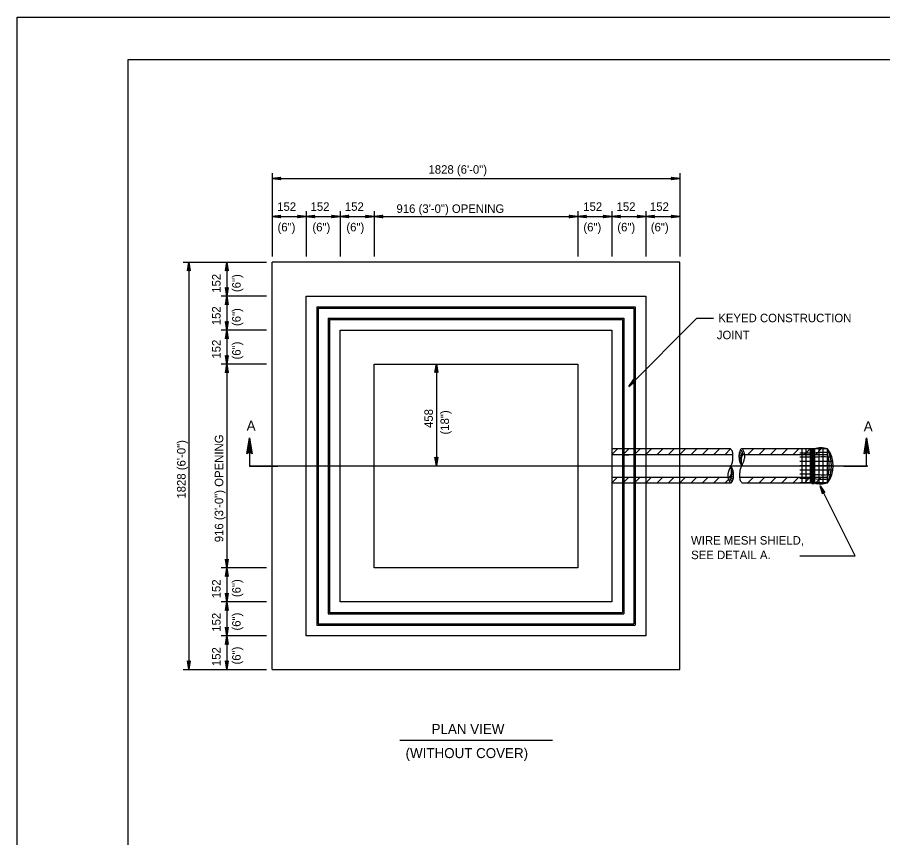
# Model space of a CAD drawing. Extents: x 638443 to 639347, y 298405 to 298999.
# Drawn here: x 638443.3 to 638749, y 298709.2 to 298999 of the extents above; entities that cross this region are included whole.
import ezdxf

# ---------------------------------------------------------------- set-up
doc = ezdxf.new("R2010")
doc.units = 0
for name, color, linetype in [('1', 7, 'Continuous'), ('2', 7, 'Continuous'), ('3', 7, 'Continuous'), ('PLT-BNDY', 7, 'Continuous')]:
    doc.layers.add(name, color=color, linetype=linetype)

msp = doc.modelspace()

# ---------------------------------------------------------------- linework, layer by layer
at = {"layer": '1'}
msp.add_lwpolyline([(639268.31, 298419.95), (639268.31, 298983.95), (638482.31, 298983.95), (638482.31, 298419.95), (639268.31, 298419.95), (639268.31, 298446.31), (639068.31, 298446.31), (639068.31, 298510.99), (639268.31, 298510.99), (639268.31, 298539.95), (639068.31, 298539.95), (639068.31, 298419.95), (639147.11, 298419.95), (639147.11, 298446.31), (639147.11, 298419.95), (639224.11, 298419.95), (639224.11, 298446.31), (639224.11, 298434), (639268.31, 298434)], dxfattribs=at)
at = {"layer": '2'}
for p, q in [((638533.34, 298943.94), (638533.34, 298914.5)), ((638533.34, 298942.07), (638677.34, 298942.07)), ((638677.34, 298943.94), (638677.34, 298914.5)), ((638545.34, 298930.5), (638545.34, 298914.5)), ((638557.34, 298930.5), (638557.34, 298914.5)), ((638569.34, 298930.5), (638569.34, 298914.5)), ((638641.34, 298930.5), (638641.34, 298914.5)), ((638653.34, 298930.5), (638653.34, 298914.5)), ((638665.34, 298930.5), (638665.34, 298914.5)), ((638533.34, 298928.63), (638545.34, 298928.63)), ((638545.34, 298928.63), (638557.34, 298928.63)), ((638557.34, 298928.63), (638569.34, 298928.63)), ((638569.34, 298928.63), (638641.34, 298928.63)), ((638641.34, 298928.63), (638653.34, 298928.63)), ((638653.34, 298928.63), (638665.34, 298928.63)), ((638665.34, 298928.63), (638677.34, 298928.63)), ((638501.88, 298912.5), (638531.34, 298912.5)), ((638503.88, 298912.5), (638503.88, 298768.63)), ((638517.34, 298912.5), (638517.34, 298900.5)), ((638677.34, 298912.5), (638533.34, 298912.5)), ((638533.34, 298768.63), (638533.34, 298912.5)), ((638677.34, 298768.63), (638677.34, 298912.5)), ((638515.34, 298900.63), (638531.34, 298900.63)), ((638517.34, 298900.5), (638517.34, 298888.5)), ((638545.34, 298900.5), (638665.34, 298900.5)), ((638545.34, 298780.5), (638545.34, 298900.5)), ((638665.34, 298900.5), (638665.34, 298780.5)), ((638549.09, 298896.75), (638549.09, 298784.25)), ((638549.09, 298896.75), (638661.59, 298896.75)), ((638549.59, 298896.25), (638549.59, 298784.75)), ((638549.59, 298896.25), (638661.09, 298896.25)), ((638661.09, 298896.25), (638661.09, 298784.75)), ((638661.59, 298896.75), (638661.59, 298784.25)), ((638553.09, 298892.75), (638553.09, 298788.25)), ((638553.09, 298892.75), (638657.59, 298892.75)), ((638657.59, 298892.75), (638657.59, 298788.25)), ((638553.59, 298892.25), (638553.59, 298788.75)), ((638553.59, 298892.25), (638657.09, 298892.25)), ((638657.09, 298892.25), (638657.09, 298788.75)), ((638515.34, 298888.63), (638531.34, 298888.63)), ((638517.34, 298888.5), (638517.34, 298876.5)), ((638557.34, 298888.5), (638653.34, 298888.5)), ((638557.34, 298792.5), (638557.34, 298888.5)), ((638653.34, 298888.5), (638653.34, 298792.5)), ((638515.34, 298876.63), (638531.34, 298876.63)), ((638517.34, 298876.5), (638517.34, 298804.5)), ((638569.34, 298876.5), (638641.34, 298876.5)), ((638569.34, 298804.5), (638569.34, 298876.5)), ((638591.34, 298876.57), (638591.34, 298840.57)), ((638641.34, 298876.5), (638641.34, 298804.5)), ((638525.34, 298850.5), (638525.34, 298840.5)), ((638743.34, 298840.5), (638743.34, 298850.5)), ((638653.34, 298844.57), (638655.34, 298846.57)), ((638663.26, 298846.57), (638653.34, 298846.57)), ((638657.34, 298844.57), (638659.34, 298846.57)), ((638661.34, 298844.57), (638663.34, 298846.57)), ((638695.29, 298846.57), (638663.26, 298846.57)), ((638665.34, 298844.57), (638667.34, 298846.57)), ((638669.34, 298844.57), (638671.34, 298846.57)), ((638673.34, 298844.57), (638675.34, 298846.57)), ((638677.34, 298844.57), (638679.34, 298846.57)), ((638681.34, 298844.57), (638683.34, 298846.57)), ((638685.34, 298844.57), (638687.34, 298846.57)), ((638689.34, 298844.57), (638691.34, 298846.57)), ((638729.54, 298846.57), (638699.3, 298846.57)), ((638699.3, 298846.52), (638699.34, 298846.57)), ((638701.34, 298844.57), (638703.34, 298846.57)), ((638705.34, 298844.57), (638707.34, 298846.57)), ((638709.34, 298844.57), (638711.34, 298846.57)), ((638713.34, 298844.57), (638715.34, 298846.57)), ((638717.34, 298844.57), (638719.34, 298846.57)), ((638729.54, 298846.57), (638719.77, 298846.57)), ((638720.54, 298834.57), (638720.54, 298846.57)), ((638721.34, 298844.57), (638723.34, 298846.57)), ((638722.04, 298834.57), (638722.04, 298846.57)), ((638723.54, 298834.57), (638723.54, 298846.57)), ((638723.94, 298834.35), (638723.94, 298846.73)), ((638723.94, 298846.73), (638724.8, 298846.73)), ((638723.99, 298834.35), (638723.99, 298846.73)), ((638724.05, 298834.35), (638724.05, 298846.73)), ((638724.12, 298834.35), (638724.12, 298846.73)), ((638724.18, 298834.35), (638724.18, 298846.73)), ((638724.24, 298834.35), (638724.24, 298846.73)), ((638724.3, 298834.35), (638724.3, 298846.73)), ((638724.37, 298834.35), (638724.37, 298846.73)), ((638724.43, 298834.35), (638724.43, 298846.73)), ((638724.49, 298834.35), (638724.49, 298846.73)), ((638724.55, 298834.35), (638724.55, 298846.73)), ((638724.61, 298834.35), (638724.61, 298846.73)), ((638724.68, 298834.35), (638724.68, 298846.73)), ((638724.74, 298834.35), (638724.74, 298846.73)), ((638724.8, 298834.35), (638724.8, 298846.73)), ((638725.04, 298834.57), (638725.04, 298846.57)), ((638725.34, 298844.57), (638727.34, 298846.57)), ((638726.54, 298834.22), (638726.54, 298846.9)), ((638728.04, 298834.25), (638728.04, 298846.87)), ((638729.54, 298834.57), (638729.54, 298846.57)), ((638729.54, 298834.57), (638729.54, 298846.57)), ((638653.34, 298844.57), (638696, 298844.57)), ((638659.34, 298844.31), (638657.34, 298844.31)), ((638693.34, 298844.57), (638695.29, 298846.52)), ((638700.34, 298844.57), (638729.54, 298844.57)), ((638725.05, 298843.57), (638719.7, 298843.57)), ((638724.77, 298845.07), (638719.79, 298845.07)), ((638525.34, 298840.57), (638743.79, 298840.57)), ((638525.34, 298840.5), (638535.34, 298840.5)), ((638731.54, 298840.57), (638719.73, 298840.57)), ((638731.43, 298842.07), (638719.77, 298842.07)), ((638735.34, 298840.5), (638743.34, 298840.5)), ((638731.43, 298839.07), (638719.75, 298839.07)), ((638725.05, 298837.57), (638719.79, 298837.57)), ((638653.34, 298834.57), (638655.34, 298836.57)), ((638653.34, 298836.57), (638694.36, 298836.57)), ((638653.34, 298834.57), (638663.26, 298834.57)), ((638657.34, 298834.57), (638659.34, 298836.57)), ((638661.34, 298834.57), (638663.34, 298836.57)), ((638663.26, 298834.57), (638695.29, 298834.57)), ((638665.34, 298834.57), (638667.34, 298836.57)), ((638669.34, 298834.57), (638671.34, 298836.57)), ((638673.34, 298834.57), (638675.34, 298836.57)), ((638677.34, 298834.57), (638679.34, 298836.57)), ((638681.34, 298834.57), (638683.34, 298836.57)), ((638685.34, 298834.57), (638687.34, 298836.57)), ((638689.34, 298834.57), (638691.34, 298836.57)), ((638693.34, 298834.57), (638694.52, 298835.74)), ((638698.74, 298836.57), (638729.54, 298836.57)), ((638699.3, 298836.52), (638699.34, 298836.57)), ((638699.3, 298834.57), (638729.54, 298834.57)), ((638701.34, 298834.57), (638703.34, 298836.57)), ((638705.34, 298834.57), (638707.34, 298836.57)), ((638709.34, 298834.57), (638711.34, 298836.57)), ((638713.34, 298834.57), (638715.34, 298836.57)), ((638717.34, 298834.57), (638719.34, 298836.57)), ((638724.95, 298836.07), (638719.75, 298836.07)), ((638729.54, 298834.57), (638719.75, 298834.57)), ((638721.34, 298834.57), (638723.34, 298836.57)), ((638725.34, 298834.57), (638727.34, 298836.57)), ((638719.75, 298808.75), (638739.25, 298808.75)), ((638515.34, 298804.63), (638531.34, 298804.63)), ((638517.34, 298804.5), (638517.34, 298792.5)), ((638641.34, 298804.5), (638569.34, 298804.5)), ((638515.34, 298792.63), (638531.34, 298792.63)), ((638517.34, 298792.5), (638517.34, 298780.5)), ((638653.34, 298792.5), (638557.34, 298792.5)), ((638553.59, 298788.75), (638657.09, 298788.75)), ((638553.09, 298788.25), (638657.59, 298788.25)), ((638549.09, 298784.25), (638661.59, 298784.25)), ((638549.59, 298784.75), (638661.09, 298784.75)), ((638515.34, 298780.63), (638531.34, 298780.63)), ((638517.34, 298780.5), (638517.34, 298768.63)), ((638665.34, 298780.5), (638545.34, 298780.5)), ((638501.88, 298768.63), (638531.34, 298768.63)), ((638677.34, 298768.5), (638533.34, 298768.5)), ((638578.42, 298743.72), (638632.32, 298743.72))]:
    msp.add_line(p, q, dxfattribs=at)
for points in [[(638638.44, 298928.99), (638638.54, 298928.78), (638641.34, 298928.63), (638638.44, 298928.99), (638638.29, 298929.12), (638641.34, 298928.63), (638638.55, 298928.49), (638638.44, 298928.28), (638641.34, 298928.63), (638638.29, 298928.14), (638638.44, 298928.28)], [(638644.25, 298928.27), (638644.14, 298928.48), (638641.34, 298928.63), (638644.25, 298928.27), (638644.4, 298928.14), (638641.34, 298928.63), (638644.14, 298928.77), (638644.24, 298928.98), (638641.34, 298928.63), (638644.4, 298929.12), (638644.24, 298928.98)], [(638524.66, 298845.05), (638525.05, 298845.26), (638525.34, 298850.5), (638524.66, 298845.05), (638524.42, 298844.77), (638525.34, 298850.5), (638525.6, 298845.26), (638525.99, 298845.07), (638525.34, 298850.5), (638526.25, 298844.77), (638525.99, 298845.07)], [(638742.66, 298845.05), (638743.05, 298845.26), (638743.34, 298850.5), (638742.66, 298845.05), (638742.42, 298844.77), (638743.34, 298850.5), (638743.6, 298845.26), (638743.99, 298845.07), (638743.34, 298850.5), (638744.25, 298844.77), (638743.99, 298845.07)], [(638591.71, 298843.47), (638591.5, 298843.36), (638591.34, 298840.57), (638591.71, 298843.47), (638591.83, 298843.62), (638591.34, 298840.57), (638591.2, 298843.36), (638591, 298843.46), (638591.34, 298840.57), (638590.86, 298843.62), (638591, 298843.46)]]:
    msp.add_lwpolyline(points, dxfattribs=at)
for centre, radius, start, end in [((638727.11, 298838.74), 8.18, 72.7594, 106.3688), ((638721.54, 298840.57), 10, 323.1301, 36.8699), ((638716.8, 298840.57), 14.08, 334.7727, 25.2273), ((638698.62, 298843.22), 0.422, 10.9894, 140.8654), ((638698.49, 298843.73), 0.654, 350.3069, 105.1317), ((638697.99, 298844.03), 1.37, 2.757, 70.3813), ((638697.79, 298844.54), 1.85, 354.8555, 59.6708), ((638727.66, 298830.23), 15.1, 79.266, 101.0155), ((638728.05, 298813.1), 30.62, 84.3259, 95.6361), ((638712.94, 298840.57), 17.2, 344.8363, 15.1637), ((638698.66, 298842.83), 0.329, 8.8886, 171.1114), ((638698.71, 298842.32), 0.286, 14.4815, 191.8386), ((638698.76, 298841.97), 0.202, 26.1102, 221.1114), ((638698.88, 298841.57), 0.197, 346.8875, 261.2044), ((638699.06, 298841.1), 0.121, 316.6855, 259.5583), ((638695.53, 298840.03), 0.121, 136.6855, 79.5583), ((638696.1, 298837.4), 0.654, 170.3069, 285.1317), ((638695.71, 298839.57), 0.197, 166.8875, 81.2044), ((638695.96, 298837.91), 0.422, 190.9894, 320.8654), ((638695.88, 298838.81), 0.286, 194.4815, 11.8386), ((638695.93, 298838.31), 0.329, 188.8886, 351.1114), ((638695.83, 298839.16), 0.202, 206.1102, 41.1114), ((638728.05, 298868.03), 30.62, 264.3639, 275.6741), ((638696.8, 298836.59), 1.85, 174.8555, 239.6708), ((638696.6, 298837.1), 1.37, 182.757, 250.3813), ((638727.66, 298850.9), 15.1, 258.9845, 280.734), ((638727.11, 298842.38), 8.18, 253.6312, 287.2406)]:
    msp.add_arc(centre, radius, start, end, dxfattribs=at)
for points in [[(638695.29, 298846.57), (638695.66, 298846.14), (638695.88, 298845.51), (638696, 298844.73), (638696.01, 298844.03), (638696, 298843.1), (638695.94, 298842.41), (638695.81, 298841.71), (638695.59, 298841.09), (638695.27, 298840.56), (638694.98, 298839.78), (638694.77, 298839.22), (638694.53, 298838.53), (638694.38, 298838), (638694.29, 298837.38), (638694.31, 298836.88), (638694.36, 298836.36), (638694.53, 298835.86), (638694.73, 298835.29), (638694.98, 298834.88), (638695.29, 298834.57), (638695.66, 298834.71), (638695.87, 298834.99), (638696, 298835.36), (638696.16, 298835.75), (638696.26, 298836.29), (638696.35, 298836.85), (638696.35, 298837.31), (638696.33, 298837.77), (638696.26, 298838.27), (638696.2, 298838.74), (638696.07, 298839.17), (638695.88, 298839.63), (638695.64, 298839.98), (638695.55, 298840.22), (638695.33, 298840.56)], [(638699.3, 298834.57), (638698.93, 298834.99), (638698.71, 298835.62), (638698.59, 298836.4), (638698.58, 298837.11), (638698.59, 298838.03), (638698.65, 298838.72), (638698.78, 298839.43), (638699, 298840.04), (638699.32, 298840.58), (638699.61, 298841.35), (638699.82, 298841.91), (638700.06, 298842.6), (638700.21, 298843.14), (638700.3, 298843.75), (638700.28, 298844.25), (638700.23, 298844.77), (638700.06, 298845.27), (638699.86, 298845.84), (638699.61, 298846.25), (638699.3, 298846.57), (638698.93, 298846.42), (638698.72, 298846.14), (638698.59, 298845.77), (638698.43, 298845.38), (638698.33, 298844.84), (638698.24, 298844.29), (638698.24, 298843.82), (638698.26, 298843.36), (638698.33, 298842.86), (638698.39, 298842.39), (638698.52, 298841.97), (638698.71, 298841.5), (638698.95, 298841.15), (638699.04, 298840.91), (638699.26, 298840.58)], [(638700.23, 298844.57), (638699.87, 298844.51), (638699.61, 298844.34), (638699.35, 298844.03), (638699.19, 298843.75), (638699.04, 298843.3), (638699, 298842.82), (638698.98, 298842.41), (638699, 298842.04), (638699.08, 298841.6), (638699.13, 298841.24), (638699.21, 298840.98), (638699.32, 298840.61)], [(638694.36, 298836.57), (638694.72, 298836.62), (638694.98, 298836.79), (638695.24, 298837.11), (638695.4, 298837.38), (638695.55, 298837.83), (638695.59, 298838.31), (638695.61, 298838.72), (638695.59, 298839.09), (638695.51, 298839.54), (638695.46, 298839.89), (638695.38, 298840.15), (638695.27, 298840.52)]]:
    msp.add_spline(points, degree=3, dxfattribs=at)
at = {"layer": '3'}
for p, q in [((638659.28, 298868.62), (638683.28, 298892.62)), ((638683.28, 298892.75), (638689.28, 298892.75)), ((638723.94, 298834.35), (638724.8, 298834.35)), ((638739.25, 298808.75), (638726.89, 298833.46))]:
    msp.add_line(p, q, dxfattribs=at)
for points in [[(638536.25, 298941.7), (638536.14, 298941.91), (638533.34, 298942.07), (638536.25, 298941.7), (638536.4, 298941.58), (638533.34, 298942.07), (638536.14, 298942.21), (638536.24, 298942.41), (638533.34, 298942.07), (638536.4, 298942.55), (638536.24, 298942.41)], [(638674.44, 298942.43), (638674.54, 298942.22), (638677.34, 298942.07), (638674.44, 298942.43), (638674.29, 298942.56), (638677.34, 298942.07), (638674.55, 298941.93), (638674.44, 298941.72), (638677.34, 298942.07), (638674.29, 298941.58), (638674.44, 298941.72)], [(638536.25, 298928.27), (638536.14, 298928.48), (638533.34, 298928.63), (638536.25, 298928.27), (638536.4, 298928.14), (638533.34, 298928.63), (638536.14, 298928.77), (638536.24, 298928.98), (638533.34, 298928.63), (638536.4, 298929.12), (638536.24, 298928.98)], [(638542.44, 298928.99), (638542.54, 298928.78), (638545.34, 298928.63), (638542.44, 298928.99), (638542.29, 298929.12), (638545.34, 298928.63), (638542.55, 298928.49), (638542.44, 298928.28), (638545.34, 298928.63), (638542.29, 298928.14), (638542.44, 298928.28)], [(638548.25, 298928.27), (638548.14, 298928.48), (638545.34, 298928.63), (638548.25, 298928.27), (638548.4, 298928.14), (638545.34, 298928.63), (638548.14, 298928.77), (638548.24, 298928.98), (638545.34, 298928.63), (638548.4, 298929.12), (638548.24, 298928.98)], [(638554.44, 298928.99), (638554.54, 298928.78), (638557.34, 298928.63), (638554.44, 298928.99), (638554.29, 298929.12), (638557.34, 298928.63), (638554.55, 298928.49), (638554.44, 298928.28), (638557.34, 298928.63), (638554.29, 298928.14), (638554.44, 298928.28)], [(638560.25, 298928.27), (638560.14, 298928.48), (638557.34, 298928.63), (638560.25, 298928.27), (638560.4, 298928.14), (638557.34, 298928.63), (638560.14, 298928.77), (638560.24, 298928.98), (638557.34, 298928.63), (638560.4, 298929.12), (638560.24, 298928.98)], [(638566.44, 298928.99), (638566.54, 298928.78), (638569.34, 298928.63), (638566.44, 298928.99), (638566.29, 298929.12), (638569.34, 298928.63), (638566.55, 298928.49), (638566.44, 298928.28), (638569.34, 298928.63), (638566.29, 298928.14), (638566.44, 298928.28)], [(638572.25, 298928.27), (638572.14, 298928.48), (638569.34, 298928.63), (638572.25, 298928.27), (638572.4, 298928.14), (638569.34, 298928.63), (638572.14, 298928.77), (638572.24, 298928.98), (638569.34, 298928.63), (638572.4, 298929.12), (638572.24, 298928.98)], [(638650.44, 298928.99), (638650.54, 298928.78), (638653.34, 298928.63), (638650.44, 298928.99), (638650.29, 298929.12), (638653.34, 298928.63), (638650.55, 298928.49), (638650.44, 298928.28), (638653.34, 298928.63), (638650.29, 298928.14), (638650.44, 298928.28)], [(638656.25, 298928.27), (638656.14, 298928.48), (638653.34, 298928.63), (638656.25, 298928.27), (638656.4, 298928.14), (638653.34, 298928.63), (638656.14, 298928.77), (638656.24, 298928.98), (638653.34, 298928.63), (638656.4, 298929.12), (638656.24, 298928.98)], [(638662.44, 298928.99), (638662.54, 298928.78), (638665.34, 298928.63), (638662.44, 298928.99), (638662.29, 298929.12), (638665.34, 298928.63), (638662.55, 298928.49), (638662.44, 298928.28), (638665.34, 298928.63), (638662.29, 298928.14), (638662.44, 298928.28)], [(638668.25, 298928.27), (638668.14, 298928.48), (638665.34, 298928.63), (638668.25, 298928.27), (638668.4, 298928.14), (638665.34, 298928.63), (638668.14, 298928.77), (638668.24, 298928.98), (638665.34, 298928.63), (638668.4, 298929.12), (638668.24, 298928.98)], [(638674.44, 298928.99), (638674.54, 298928.78), (638677.34, 298928.63), (638674.44, 298928.99), (638674.29, 298929.12), (638677.34, 298928.63), (638674.55, 298928.49), (638674.44, 298928.28), (638677.34, 298928.63), (638674.29, 298928.14), (638674.44, 298928.28)], [(638503.52, 298909.6), (638503.73, 298909.7), (638503.88, 298912.5), (638503.52, 298909.6), (638503.39, 298909.45), (638503.88, 298912.5), (638504.02, 298909.71), (638504.23, 298909.6), (638503.88, 298912.5), (638504.37, 298909.45), (638504.23, 298909.6)], [(638516.98, 298909.6), (638517.19, 298909.7), (638517.34, 298912.5), (638516.98, 298909.6), (638516.85, 298909.45), (638517.34, 298912.5), (638517.48, 298909.71), (638517.69, 298909.6), (638517.34, 298912.5), (638517.83, 298909.45), (638517.69, 298909.6)], [(638517.71, 298903.41), (638517.5, 298903.3), (638517.34, 298900.5), (638517.71, 298903.41), (638517.83, 298903.56), (638517.34, 298900.5), (638517.2, 298903.3), (638517, 298903.4), (638517.34, 298900.5), (638516.86, 298903.56), (638517, 298903.4)], [(638516.98, 298897.6), (638517.19, 298897.7), (638517.34, 298900.5), (638516.98, 298897.6), (638516.85, 298897.45), (638517.34, 298900.5), (638517.48, 298897.71), (638517.69, 298897.6), (638517.34, 298900.5), (638517.83, 298897.45), (638517.69, 298897.6)], [(638517.71, 298891.41), (638517.5, 298891.3), (638517.34, 298888.5), (638517.71, 298891.41), (638517.83, 298891.56), (638517.34, 298888.5), (638517.2, 298891.3), (638517, 298891.4), (638517.34, 298888.5), (638516.86, 298891.56), (638517, 298891.4)], [(638516.98, 298885.6), (638517.19, 298885.7), (638517.34, 298888.5), (638516.98, 298885.6), (638516.85, 298885.45), (638517.34, 298888.5), (638517.48, 298885.71), (638517.69, 298885.6), (638517.34, 298888.5), (638517.83, 298885.45), (638517.69, 298885.6)], [(638517.71, 298879.41), (638517.5, 298879.3), (638517.34, 298876.5), (638517.71, 298879.41), (638517.83, 298879.56), (638517.34, 298876.5), (638517.2, 298879.3), (638517, 298879.4), (638517.34, 298876.5), (638516.86, 298879.56), (638517, 298879.4)], [(638516.98, 298873.6), (638517.19, 298873.7), (638517.34, 298876.5), (638516.98, 298873.6), (638516.85, 298873.45), (638517.34, 298876.5), (638517.48, 298873.71), (638517.69, 298873.6), (638517.34, 298876.5), (638517.83, 298873.45), (638517.69, 298873.6)], [(638590.98, 298873.66), (638591.19, 298873.77), (638591.34, 298876.57), (638590.98, 298873.66), (638590.85, 298873.51), (638591.34, 298876.57), (638591.48, 298873.77), (638591.69, 298873.67), (638591.34, 298876.57), (638591.83, 298873.51), (638591.69, 298873.67)], [(638661.59, 298870.42), (638661.36, 298870.49), (638659.28, 298868.62), (638661.59, 298870.42), (638661.78, 298870.44), (638659.28, 298868.62), (638661.15, 298870.7), (638661.08, 298870.92), (638659.28, 298868.62), (638661.09, 298871.13), (638661.08, 298870.92)], [(638727.81, 298830.87), (638727.94, 298831.05), (638726.89, 298833.46), (638727.81, 298830.87), (638727.76, 298830.7), (638726.89, 298833.46), (638728.18, 298831.18), (638728.4, 298831.18), (638726.89, 298833.46), (638728.58, 298831.11), (638728.4, 298831.18)], [(638517.71, 298807.41), (638517.5, 298807.3), (638517.34, 298804.5), (638517.71, 298807.41), (638517.83, 298807.56), (638517.34, 298804.5), (638517.2, 298807.3), (638517, 298807.4), (638517.34, 298804.5), (638516.86, 298807.56), (638517, 298807.4)], [(638516.98, 298801.6), (638517.19, 298801.7), (638517.34, 298804.5), (638516.98, 298801.6), (638516.85, 298801.45), (638517.34, 298804.5), (638517.48, 298801.71), (638517.69, 298801.6), (638517.34, 298804.5), (638517.83, 298801.45), (638517.69, 298801.6)], [(638517.71, 298795.41), (638517.5, 298795.3), (638517.34, 298792.5), (638517.71, 298795.41), (638517.83, 298795.56), (638517.34, 298792.5), (638517.2, 298795.3), (638517, 298795.4), (638517.34, 298792.5), (638516.86, 298795.56), (638517, 298795.4)], [(638516.98, 298789.6), (638517.19, 298789.7), (638517.34, 298792.5), (638516.98, 298789.6), (638516.85, 298789.45), (638517.34, 298792.5), (638517.48, 298789.71), (638517.69, 298789.6), (638517.34, 298792.5), (638517.83, 298789.45), (638517.69, 298789.6)], [(638517.71, 298783.41), (638517.5, 298783.3), (638517.34, 298780.5), (638517.71, 298783.41), (638517.83, 298783.56), (638517.34, 298780.5), (638517.2, 298783.3), (638517, 298783.4), (638517.34, 298780.5), (638516.86, 298783.56), (638517, 298783.4)], [(638516.98, 298777.6), (638517.19, 298777.7), (638517.34, 298780.5), (638516.98, 298777.6), (638516.85, 298777.45), (638517.34, 298780.5), (638517.48, 298777.71), (638517.69, 298777.6), (638517.34, 298780.5), (638517.83, 298777.45), (638517.69, 298777.6)], [(638504.25, 298771.54), (638504.04, 298771.43), (638503.88, 298768.63), (638504.25, 298771.54), (638504.37, 298771.69), (638503.88, 298768.63), (638503.74, 298771.43), (638503.54, 298771.53), (638503.88, 298768.63), (638503.4, 298771.69), (638503.54, 298771.53)], [(638517.71, 298771.54), (638517.5, 298771.43), (638517.34, 298768.63), (638517.71, 298771.54), (638517.83, 298771.69), (638517.34, 298768.63), (638517.2, 298771.43), (638517, 298771.53), (638517.34, 298768.63), (638516.86, 298771.69), (638517, 298771.53)]]:
    msp.add_lwpolyline(points, dxfattribs=at)
at = {"layer": 'PLT-BNDY'}
msp.add_lwpolyline([(638443.31, 298998.95), (639284.31, 298998.95), (639284.31, 298404.95), (638443.31, 298404.95)], close=True, dxfattribs=at)

# ---------------------------------------------------------------- texts
at = {"layer": '2'}
for s, p in [('458', (638590.12, 298853.93)), ('(18")', (638595.81, 298851.61))]:
    msp.add_text(s, height=3, rotation=90, dxfattribs=at).set_placement(p)
for s, p in [('A', (638524.33, 298853)), ('A', (638742.33, 298852.77)), ('PLAN VIEW', (638589.66, 298745.86)), ('(WITHOUT COVER)', (638580.48, 298737.36))]:
    msp.add_text(s, height=3.53, dxfattribs=at).set_placement(p)
at = {"layer": '3'}
for s, p in [('1828 (6\'-0")', (638588.56, 298943.73)), ('152', (638535.1, 298930.61)), ('152', (638546.89, 298930.61)), ('152', (638559.02, 298930.61)), ('916 (3\'-0") OPENING', (638577.25, 298929.89)), ('152', (638643.23, 298930.61)), ('152', (638655.01, 298930.61)), ('152', (638666.8, 298930.61)), ('(6")', (638535.23, 298923.37)), ('(6")', (638547.55, 298923.37)), ('(6")', (638559.55, 298923.37)), ('(6")', (638643.28, 298923.37)), ('(6")', (638655.27, 298923.37)), ('(6")', (638667.08, 298923.37)), ('KEYED CONSTRUCTION', (638690.94, 298891.27)), ('JOINT', (638690.42, 298885.27)), ('WIRE MESH SHIELD,', (638681.31, 298812.75)), ('SEE DETAIL A.', (638681.35, 298807.61))]:
    msp.add_text(s, height=3, dxfattribs=at).set_placement(p)
for s, p in [('152', (638515.11, 298901.66)), ('(6")', (638522.21, 298901.92)), ('152', (638515.11, 298890.21)), ('(6")', (638522.21, 298889.93)), ('152', (638515.11, 298878.42)), ('(6")', (638522.21, 298878.12)), ('916 (3\'-0") OPENING', (638516.06, 298813.58)), ('1828 (6\'-0")', (638502.74, 298828.97)), ('152', (638515.11, 298793.77)), ('(6")', (638522.21, 298794.2)), ('152', (638515.11, 298781.98)), ('(6")', (638522.21, 298782.39)), ('152', (638515.11, 298769.84)), ('(6")', (638522.21, 298770.4))]:
    msp.add_text(s, height=3, rotation=90, dxfattribs=at).set_placement(p)

doc.saveas('drawing.dxf')
